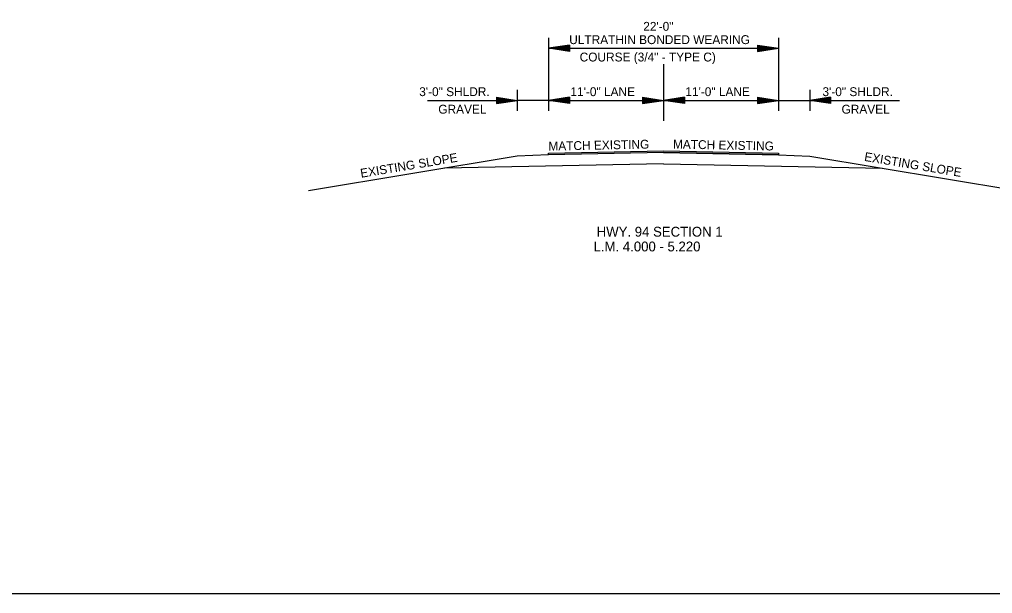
# Model space of a CAD drawing. Extents: x 2261938 to 2263136, y -3124572 to -3124216.
# Drawn here: x 2262700.3 to 2262793.4, y -3124556.1 to -3124501.1 of the extents above; entities that cross this region are included whole.
import ezdxf

# ---------------------------------------------------------------- set-up
doc = ezdxf.new("R2010")
doc.units = 0
for name, color, linetype in [('DSN_DRFT_Common-Annotations', 7, 'Continuous'), ('DSN_DRFT_Common-Line', 7, 'Continuous'), ('DSN_DRFT_Dimension', 7, 'Continuous')]:
    doc.layers.add(name, color=color, linetype=linetype)

msp = doc.modelspace()

# ---------------------------------------------------------------- linework, layer by layer
at = {"layer": 'DSN_DRFT_Common-Line'}
for p, q in [((2262750.939, -3124502.853), (2262750.939, -3124509.853)), ((2262772.939, -3124502.853), (2262772.939, -3124509.853)), ((2262761.939, -3124505.393), (2262761.939, -3124510.803)), ((2262747.939, -3124507.853), (2262747.939, -3124509.853)), ((2262775.939, -3124507.853), (2262775.939, -3124509.853)), ((2262747.939, -3124514.193), (2262727.939, -3124517.526)), ((2262750.939, -3124514.073), (2262747.939, -3124514.193)), ((2262761.939, -3124513.853), (2262750.939, -3124514.073)), ((2262761.939, -3124513.853), (2262772.939, -3124514.073)), ((2262772.939, -3124514.073), (2262775.939, -3124514.193)), ((2262775.939, -3124514.193), (2262795.939, -3124517.526)), ((2262761.939, -3124514.936), (2262740.961, -3124515.355)), ((2262761.939, -3124514.936), (2262782.916, -3124515.355))]:
    msp.add_line(p, q, dxfattribs=at)
for points in [[(2262676.902, -3124446.104), (2262676.902, -3124556.104), (2262846.902, -3124556.104), (2262846.902, -3124446.104)], [(2262772.939, -3124514.073), (2262761.939, -3124513.853), (2262750.939, -3124514.073), (2262750.939, -3124513.906), (2262761.939, -3124513.686), (2262772.939, -3124513.906)]]:
    msp.add_lwpolyline(points, close=True, dxfattribs=at)
at = {"layer": 'DSN_DRFT_Dimension'}
for p, q in [((2262752.939, -3124503.553), (2262750.939, -3124503.853)), ((2262752.939, -3124503.553), (2262752.939, -3124504.153)), ((2262770.939, -3124503.553), (2262772.939, -3124503.853)), ((2262770.939, -3124503.553), (2262770.939, -3124504.153)), ((2262752.939, -3124504.153), (2262750.939, -3124503.853)), ((2262750.939, -3124503.853), (2262772.939, -3124503.853)), ((2262752.939, -3124503.603), (2262751.273, -3124503.853)), ((2262752.939, -3124504.103), (2262751.273, -3124503.853)), ((2262752.939, -3124503.654), (2262751.617, -3124503.853)), ((2262752.939, -3124504.052), (2262751.617, -3124503.853)), ((2262752.939, -3124503.704), (2262751.95, -3124503.853)), ((2262752.939, -3124504.002), (2262751.95, -3124503.853)), ((2262752.939, -3124503.756), (2262752.289, -3124503.853)), ((2262752.939, -3124503.951), (2262752.289, -3124503.853)), ((2262752.939, -3124503.806), (2262752.623, -3124503.853)), ((2262752.939, -3124503.9), (2262752.623, -3124503.853)), ((2262770.939, -3124503.603), (2262772.605, -3124503.853)), ((2262770.939, -3124503.654), (2262772.261, -3124503.853)), ((2262770.939, -3124503.704), (2262771.928, -3124503.853)), ((2262770.939, -3124503.756), (2262771.589, -3124503.853)), ((2262770.939, -3124503.806), (2262771.255, -3124503.853)), ((2262770.939, -3124504.153), (2262772.939, -3124503.853)), ((2262770.939, -3124503.951), (2262771.589, -3124503.853)), ((2262770.939, -3124504.052), (2262772.261, -3124503.853)), ((2262770.939, -3124504.103), (2262772.605, -3124503.853)), ((2262770.939, -3124504.002), (2262771.928, -3124503.853)), ((2262770.939, -3124503.9), (2262771.255, -3124503.853)), ((2262739.329, -3124508.853), (2262747.939, -3124508.853)), ((2262745.939, -3124508.553), (2262747.939, -3124508.853)), ((2262745.939, -3124508.553), (2262745.939, -3124509.153)), ((2262745.939, -3124508.603), (2262747.605, -3124508.853)), ((2262745.939, -3124508.654), (2262747.261, -3124508.853)), ((2262745.939, -3124508.704), (2262746.928, -3124508.853)), ((2262745.939, -3124508.756), (2262746.589, -3124508.853)), ((2262745.939, -3124508.806), (2262746.255, -3124508.853)), ((2262745.939, -3124509.153), (2262747.939, -3124508.853)), ((2262745.939, -3124508.951), (2262746.589, -3124508.853)), ((2262745.939, -3124509.052), (2262747.261, -3124508.853)), ((2262745.939, -3124509.103), (2262747.605, -3124508.853)), ((2262745.939, -3124509.002), (2262746.928, -3124508.853)), ((2262745.939, -3124508.9), (2262746.255, -3124508.853)), ((2262750.939, -3124508.853), (2262747.939, -3124508.853)), ((2262752.939, -3124508.553), (2262750.939, -3124508.853)), ((2262750.939, -3124508.853), (2262761.939, -3124508.853)), ((2262752.939, -3124509.153), (2262750.939, -3124508.853)), ((2262752.939, -3124508.603), (2262751.273, -3124508.853)), ((2262752.939, -3124509.103), (2262751.273, -3124508.853)), ((2262752.939, -3124508.654), (2262751.617, -3124508.853)), ((2262752.939, -3124509.052), (2262751.617, -3124508.853)), ((2262752.939, -3124508.704), (2262751.95, -3124508.853)), ((2262752.939, -3124509.002), (2262751.95, -3124508.853)), ((2262752.939, -3124508.756), (2262752.289, -3124508.853)), ((2262752.939, -3124508.951), (2262752.289, -3124508.853)), ((2262752.939, -3124508.806), (2262752.623, -3124508.853)), ((2262752.939, -3124508.9), (2262752.623, -3124508.853)), ((2262752.939, -3124508.553), (2262752.939, -3124509.153)), ((2262759.939, -3124508.553), (2262761.939, -3124508.853)), ((2262759.939, -3124508.553), (2262759.939, -3124509.153)), ((2262759.939, -3124508.603), (2262761.605, -3124508.853)), ((2262759.939, -3124508.654), (2262761.261, -3124508.853)), ((2262759.939, -3124508.704), (2262760.928, -3124508.853)), ((2262759.939, -3124508.756), (2262760.589, -3124508.853)), ((2262759.939, -3124508.806), (2262760.255, -3124508.853)), ((2262759.939, -3124509.153), (2262761.939, -3124508.853)), ((2262759.939, -3124508.951), (2262760.589, -3124508.853)), ((2262759.939, -3124509.052), (2262761.261, -3124508.853)), ((2262759.939, -3124509.103), (2262761.605, -3124508.853)), ((2262759.939, -3124509.002), (2262760.928, -3124508.853)), ((2262759.939, -3124508.9), (2262760.255, -3124508.853)), ((2262763.939, -3124508.553), (2262761.939, -3124508.853)), ((2262761.939, -3124508.853), (2262772.939, -3124508.853)), ((2262763.939, -3124509.153), (2262761.939, -3124508.853)), ((2262763.939, -3124508.603), (2262762.273, -3124508.853)), ((2262763.939, -3124509.103), (2262762.273, -3124508.853)), ((2262763.939, -3124508.654), (2262762.617, -3124508.853)), ((2262763.939, -3124509.052), (2262762.617, -3124508.853)), ((2262763.939, -3124508.704), (2262762.95, -3124508.853)), ((2262763.939, -3124509.002), (2262762.95, -3124508.853)), ((2262763.939, -3124508.756), (2262763.289, -3124508.853)), ((2262763.939, -3124508.951), (2262763.289, -3124508.853)), ((2262763.939, -3124508.806), (2262763.623, -3124508.853)), ((2262763.939, -3124508.9), (2262763.623, -3124508.853)), ((2262763.939, -3124508.553), (2262763.939, -3124509.153)), ((2262770.939, -3124508.553), (2262772.939, -3124508.853)), ((2262770.939, -3124508.553), (2262770.939, -3124509.153)), ((2262770.939, -3124508.603), (2262772.605, -3124508.853)), ((2262770.939, -3124508.654), (2262772.261, -3124508.853)), ((2262770.939, -3124508.704), (2262771.928, -3124508.853)), ((2262770.939, -3124508.756), (2262771.589, -3124508.853)), ((2262770.939, -3124508.806), (2262771.255, -3124508.853)), ((2262770.939, -3124509.153), (2262772.939, -3124508.853)), ((2262770.939, -3124508.951), (2262771.589, -3124508.853)), ((2262770.939, -3124509.052), (2262772.261, -3124508.853)), ((2262770.939, -3124509.103), (2262772.605, -3124508.853)), ((2262770.939, -3124509.002), (2262771.928, -3124508.853)), ((2262770.939, -3124508.9), (2262771.255, -3124508.853)), ((2262772.939, -3124508.853), (2262775.939, -3124508.853)), ((2262777.939, -3124508.553), (2262775.939, -3124508.853)), ((2262777.939, -3124509.153), (2262775.939, -3124508.853)), ((2262775.939, -3124508.853), (2262784.548, -3124508.853)), ((2262777.939, -3124508.603), (2262776.273, -3124508.853)), ((2262777.939, -3124509.103), (2262776.273, -3124508.853)), ((2262777.939, -3124508.654), (2262776.617, -3124508.853)), ((2262777.939, -3124509.052), (2262776.617, -3124508.853)), ((2262777.939, -3124508.704), (2262776.95, -3124508.853)), ((2262777.939, -3124509.002), (2262776.95, -3124508.853)), ((2262777.939, -3124508.756), (2262777.289, -3124508.853)), ((2262777.939, -3124508.951), (2262777.289, -3124508.853)), ((2262777.939, -3124508.806), (2262777.623, -3124508.853)), ((2262777.939, -3124508.9), (2262777.623, -3124508.853)), ((2262777.939, -3124508.553), (2262777.939, -3124509.153))]:
    msp.add_line(p, q, dxfattribs=at)

# ---------------------------------------------------------------- texts
at = {"layer": 'DSN_DRFT_Common-Annotations'}
for s, height, p in [('22\'-0"', 0.85, (2262760.001, -3124502.183)), ('ULTRATHIN BONDED WEARING', 0.85, (2262752.913, -3124503.458)), ('COURSE (3/4" - TYPE C)', 0.85, (2262753.914, -3124505.123)), ('3\'-0" SHLDR.', 0.85, (2262738.551, -3124508.443)), ('11\'-0" LANE', 0.85, (2262753.032, -3124508.443)), ('11\'-0" LANE', 0.85, (2262764.032, -3124508.443)), ('3\'-0" SHLDR.', 0.85, (2262777.161, -3124508.443)), ('GRAVEL', 0.85, (2262740.378, -3124510.123)), ('GRAVEL', 0.85, (2262778.988, -3124510.123)), ('HWY. 94 SECTION 1', 0.943, (2262755.546, -3124521.906)), ('L.M. 4.000 - 5.220', 0.943, (2262755.245, -3124523.321))]:
    msp.add_text(s, height=height, dxfattribs=at).set_placement(p)
for s, rotation, p in [('MATCH EXISTING', 1.14576, (2262750.928, -3124513.663)), ('MATCH EXISTING', 358.85424, (2262762.842, -3124513.461)), ('EXISTING SLOPE', 9.462, (2262732.986, -3124516.269)), ('EXISTING SLOPE', 350.538, (2262781.121, -3124514.641))]:
    msp.add_text(s, height=0.85, rotation=rotation, dxfattribs=at).set_placement(p)

doc.saveas('drawing.dxf')
